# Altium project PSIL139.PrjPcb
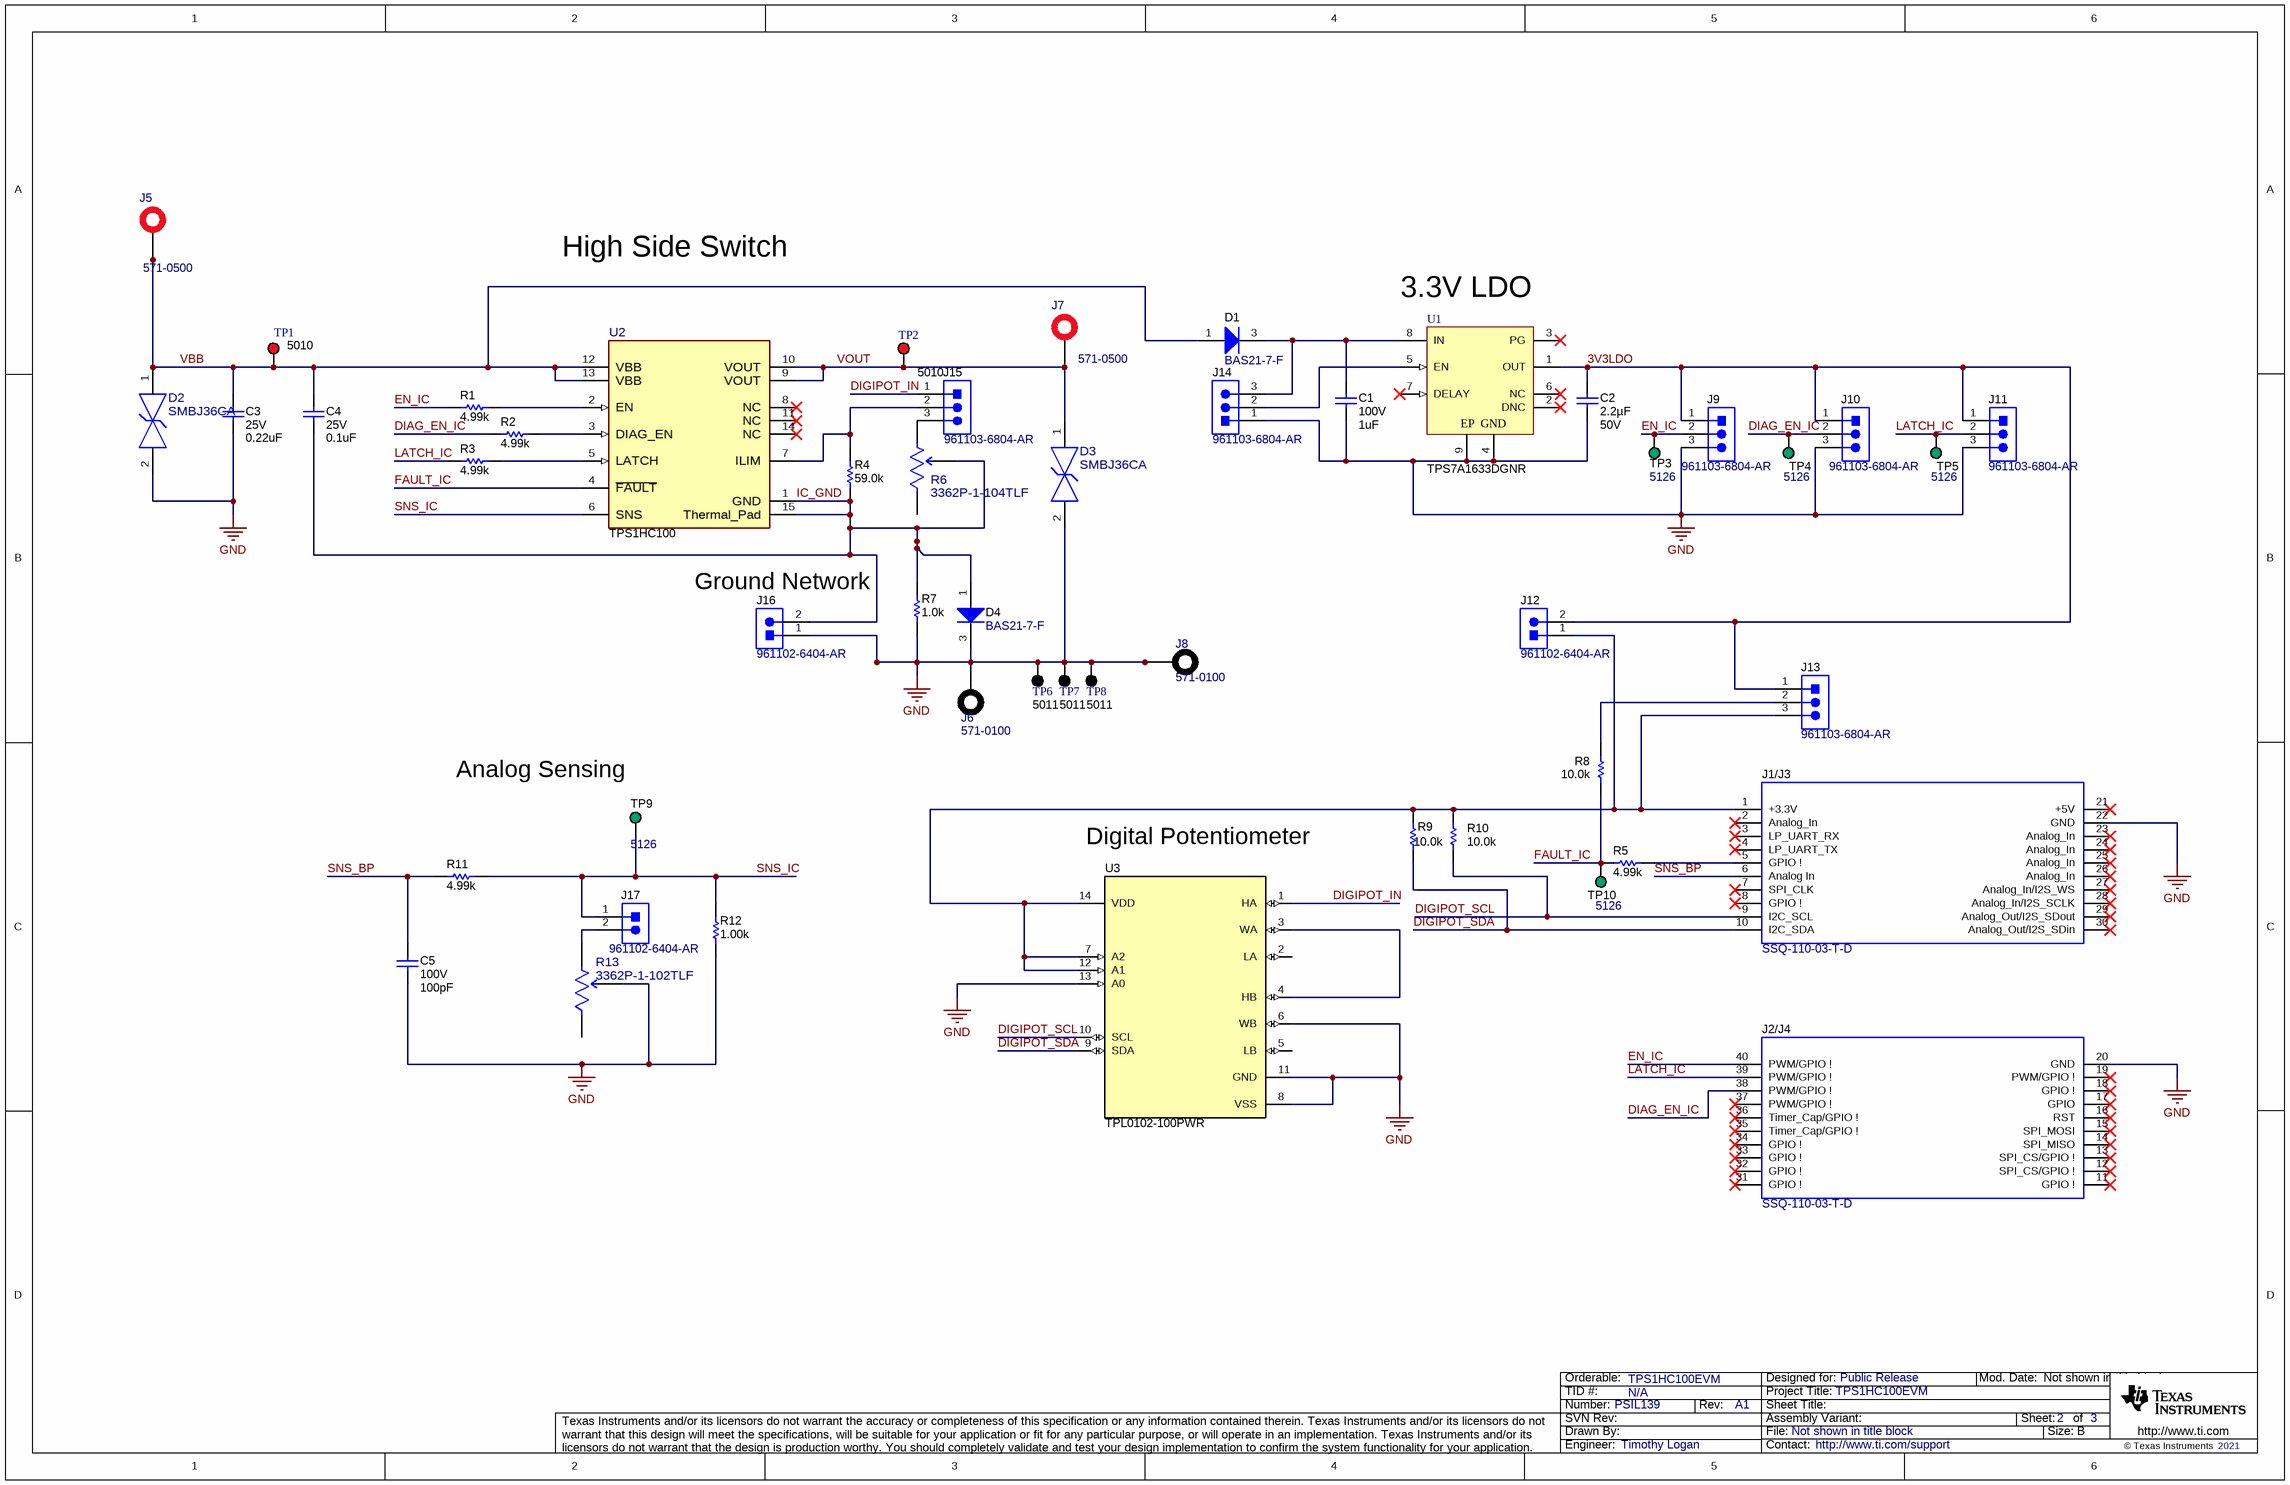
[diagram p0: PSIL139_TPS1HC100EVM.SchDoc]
CopyrightYear: 2021; EVM_Orderable: TPS1HC100EVM; PCB_Layout: Timothy Logan; PCB_Rev: A1; PRJ_Customer: Public Release; PRJ_Engineer: Timothy Logan; PRJ_Number: PSIL139; PRJ_Title: TPS1HC100EVM; SCH_Rev: A1; TechSupport: http://www.ti.com/support; TID: N/A
2 sheets, 66 parts. Net scope: global (net labels, ports and power ports of the same name join across sheets).
Board file: PSIL139_TPS1HC100EVM_PCB.PcbDoc
Sheets:
  PSIL139_TPS1HC100EVM.SchDoc
  PSIL139_Hardware.SchDoc

## Sheet PSIL139_TPS1HC100EVM.SchDoc
size 431 x 279 mm; Date: Not shown in title block; ApprovedBy: Not shown in title block; CheckedBy: Not shown in title block; Author: Not shown in title block; CompanyName: Not shown in title block; Engineer: Not shown in title block; Organization: Not shown in title block; Address1: Not shown in title block; Address2: Not shown in title block; Address3: Not shown in title block; Address4: Not shown in title block; DocumentNumber: 2; Revision: Use project parameter SCH_Rev; SheetNumber: 2; SheetTotal: 3; PageSetup: Record=PageOptions¦CenterHorizontal=True¦CenterVertical=True¦PrintScale=1.00¦XCorrection=1.00¦YCorrection=1.00¦PrintKind=0¦BorderSize=5000000¦LeftOffset=0¦BottomOffset=0¦Orientation=2¦PaperLength=1000¦PaperWidth=1000¦Scale=100¦PaperSource=15¦PrintQuality=600¦MediaType=1¦DitherType=10¦PaperKind=Letter¦PrintScaleMode=1

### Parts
C1  VDC_V: 100V  ValueDisplayed: 1uF  [0805_HV]  (hidden comment: CGA4J3X7S2A105K125AB)
C2  Cap_F: 2.2µF  VDC_V: 50V  [0805_HV]  (hidden comment: CGA4J3X7R1H225K125AB)
C3  VDC_V: 25V  ValueDisplayed: 0.22uF  [0603]  (hidden comment: CGA3E3X8R1E224K080AB)
C4  VDC_V: 25V  ValueDisplayed: 0.1uF  [0603]  (hidden comment: CGA3E2X8R1E104K080AA)
C5  VDC_V: 100V  ValueDisplayed: 100pF  [0603]  (hidden comment: GCM1885C2A101JA16D)
D1  BAS21-7-F  [SOT-23L]
D2  SMBJ36CA  [FP-SMBJ36CA_DO-214AA-0]
D3  SMBJ36CA  [FP-SMBJ36CA_DO-214AA-0]
D4  BAS21-7-F  [SOT-23L]
J1/J3  SSQ-110-03-T-D  [BoosterPack_40pin_J1J3]
J2/J4  SSQ-110-03-T-D  [BoosterPack_40pin_J2J4]
J5  571-0500  [571-0500]
J6  571-0100  [571-0100]
J7  571-0500  [571-0500]
J8  571-0100  [571-0100]
J9  961103-6804-AR  [3M_961103-68]
J10  961103-6804-AR  [3M_961103-68]
J11  961103-6804-AR  [3M_961103-68]
J12  961102-6404-AR  [3M_961102-6404-AR]
J13  961103-6804-AR  [3M_961103-68]
J14  961103-6804-AR  [3M_961103-68]
J15  961103-6804-AR  [3M_961103-68]
J16  961102-6404-AR  [3M_961102-6404-AR]
J17  961102-6404-AR  [3M_961102-6404-AR]
R1  ValueDisplayed: 4.99k  [0603]  (hidden comment: CRCW06034K99FKEA)
R2  ValueDisplayed: 4.99k  [0603]  (hidden comment: CRCW06034K99FKEA)
R3  ValueDisplayed: 4.99k  [0603]  (hidden comment: CRCW06034K99FKEA)
R4  ValueDisplayed: 59.0k  [0805_HV]  (hidden comment: ERJ-6ENF5902V)
R5  ValueDisplayed: 4.99k  [0603]  (hidden comment: CRCW06034K99FKEA)
R6  3362P-1-104TLF  [FP-3362P-1-104TLF_PTH_TRIMMER_6MM60_6MM99-MFG]
R7  ValueDisplayed: 1.0k  [0805_HV]  (hidden comment: ERJ-6GEYJ102V)
R8  ValueDisplayed: 10.0k  [0603]  (hidden comment: ERA-3ARW103V)
R9  ValueDisplayed: 10.0k  [0603]  (hidden comment: ERA-3ARW103V)
R10  ValueDisplayed: 10.0k  [0603]  (hidden comment: ERA-3ARW103V)
R11  ValueDisplayed: 4.99k  [0603]  (hidden comment: CRCW06034K99FKEA)
R12  ValueDisplayed: 1.00k  [0805_HV]  (hidden comment: ERJ-P06F1001V)
R13  3362P-1-102TLF  [FP-3362P-1-102TLF_PTH_POT_6MM6_6MM99-MFG]
TP1  5010  [Keystone5010]
TP2  5010  [Keystone5010]
TP3  5126  [Keystone5126]
TP4  5126  [Keystone5126]
TP5  5126  [Keystone5126]
TP6  5011  [Keystone5011]
TP7  5011  [Keystone5011]
TP8  5011  [Keystone5011]
TP9  5126  [Keystone5126]
TP10  5126  [Keystone5126]
U1  TPS7A1633DGNR  [DGN0008C_N]
U2  TPS1HC100  [PWP0014C-MFG]
U3  TPL0102-100PWR  [PW0014A_N]

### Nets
GND: C1.2 C2.2 C3.2 C5.1 D2.2 D3.2 D4.3(K) J1/J3.22(GND) J2/J4.20(GND) J6.1 J6.2 J8.1 J8.2 J9.3 J10.3 J11.3 J14.1 J16.1 R7.1 R12.2 R13.2(WIPER) TP6.1 TP7.1 TP8.1 U1.4(GND) U1.9(EP) U3.6(WB) U3.8(VSS) U3.11(GND) U3.13(A0)
3V3LDO: C2.1 J9.1 J10.1 J11.1 J12.2 J13.1 U1.1(OUT)
DIAG_EN_IC: J2/J4.38(PWM/GPIO_!) J10.2 R2.1 TP4.1
DIGIPOT_IN: J15.1 U3.1(HA)
DIGIPOT_SCL: J1/J3.9(I2C_SCL) R10.1 U3.10(SCL)
DIGIPOT_SDA: J1/J3.10(I2C_SDA) R9.1 U3.9(SDA)
EN_IC: J2/J4.40(PWM/GPIO_!) J9.2 R1.1 TP3.1
FAULT_IC: R5.1 R8.1 TP10.1 U2.4(~{FAULT})
IC_GND: C4.2 D4.1(A) J16.2 R4.1 R6.2(WIPER) R7.2 U2.1(GND) U2.15(Thermal_Pad)
LATCH_IC: J2/J4.39(PWM/GPIO_!) J11.2 R3.1 TP5.1
SNS_BP: C5.2 J1/J3.6(Analog_In) R11.1
SNS_IC: J17.1 R11.2 R12.1 TP9.1 U2.6(SNS)
VBB: C3.1 C4.1 D1.1(A) D2.1 J5.1 J5.2 TP1.1 U2.12(VBB) U2.13(VBB)
VOUT: D3.1 J7.1 J7.2 TP2.1 U2.9(VOUT) U2.10(VOUT)
NetC1_1: C1.1 D1.3(K) J14.3 U1.8(IN)
NetJ1/J3_1: J1/J3.1(+3.3V) J12.1 J13.3 R9.2 R10.2 U3.7(A2) U3.12(A1) U3.14(VDD)
NetJ1/J3_5: J1/J3.5(GPIO_!) R5.2
NetJ13_2: J13.2 R8.2
NetJ14_2: J14.2 U1.5(EN)
NetJ15_2: J15.2 R4.2 U2.7(ILIM)
NetJ15_3: J15.3 R6.1(CCW)
NetJ17_2: J17.2 R13.3(CW)
NetR1_2: R1.2 U2.2(EN)
NetR2_2: R2.2 U2.3(DIAG_EN)
NetR3_2: R3.2 U2.5(LATCH)
NetU3_3: U3.3(WA) U3.4(HB)

Not connected (* = marked no-connect by the designer): J1/J3 2(Analog_In)* 3(LP_UART_RX)* 4(LP_UART_TX)* 7(SPI_CLK)* 8(GPIO_!)* 21(+5V)* 23(Analog_In)* 24(Analog_In)* 25(Analog_In)* 26(Analog_In)* 27(Analog_In/I2S_WS)* 28(Analog_In/I2S_SCLK)* 29(Analog_Out/I2S_SDout)* 30(Analog_Out/I2S_SDin)*; J2/J4 11(GPIO_!)* 12(SPI_CS/GPIO_!)* 13(SPI_CS/GPIO_!)* 14(SPI_MISO)* 15(SPI_MOSI)* 16(RST)* 17(GPIO)* 18(GPIO_!)* 19(PWM/GPIO_!)* 31(GPIO_!)* 32(GPIO_!)* 33(GPIO_!)* 34(GPIO_!)* 35(Timer_Cap/GPIO_!)* 36(Timer_Cap/GPIO_!)* 37(PWM/GPIO_!)*; R6 3(CW); R13 1(CCW); U1 2(DNC)* 3(PG)* 6(NC)* 7(DELAY)*; U2 8(NC)* 11(NC)* 14(NC)*; U3 2(LA) 5(LB)

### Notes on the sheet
- High Side Switch
- (near U1) 3.3V LDO
- (near J16) Ground Network
- (near TP9) Analog Sensing
- Digital Potentiometer

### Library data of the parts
C1 = CMP-0007980-2: CAP, CERM, 1 uF, 100 V, +/- 10%, X7S, AEC-Q200 Grade 1, 0805; Manufacturer: TDK; TaMin_C: -55°C; ESR_ohm: 8.255m; Polarized: N; SizeAreaWB_mm2: 6.75; Value1: 0.008255 ohm; U/M: EA; Value: 1uF; TaMax_C: 125°C; SizeZ_mm: 1.45; SizeX_mm: 2; SizeY_mm: 1.25; Cap_Case: 0805; SizeArea_mm2: 2.5; AEC Qualified: Y; Cap_F: 1µF; IRMS_A: 2.27442A; AEC Grade: 1; AEC Category: Q200
C2 = CMP-0007977-1: CAP, CERM, 2.2 uF, 50 V, +/- 10%, X7R, AEC-Q200 Grade 1, 0805; Manufacturer: TDK; TaMin_C: -55°C; ESR_ohm: 3.288m; Polarized: N; SizeAreaWB_mm2: 6.75; Value1: 0.003288 ohm; U/M: EA; Value: 2.2uF; TaMax_C: 125°C; SizeZ_mm: 1.45; SizeX_mm: 2; SizeY_mm: 1.25; Cap_Case: 0805; SizeArea_mm2: 2.5; AEC Qualified: Y; IRMS_A: 3.60029A; AEC Grade: 1; AEC Category: Q200
C3 = CMP-0007103-2: CAP, CERM, 0.22 uF, 25 V, +/- 10%, X8R, AEC-Q200 Grade 0, 0603; Manufacturer: TDK; TaMin_C: -55°C; Polarized: N; SizeAreaWB_mm2: 4.68; Value1: Unknown; U/M: EA; Value: 0.22uF; TaMax_C: 150°C; SizeZ_mm: 1; SizeX_mm: 1.6; SizeY_mm: 0.8; SizeArea_mm2: 1.28; AEC Qualified: Y; Cap_F: 220nF; AEC Grade: 0; AEC Category: Q200
C4 = CMP-0007090-1: CAP, CERM, 0.1 uF, 25 V, +/- 10%, X8R, AEC-Q200 Grade 0, 0603; Manufacturer: TDK; TaMin_C: -55°C; Polarized: N; SizeAreaWB_mm2: 4.68; Value1: Unknown; U/M: EA; Value: 0.1uF; TaMax_C: 150°C; SizeZ_mm: 1; SizeX_mm: 1.6; SizeY_mm: 0.8; SizeArea_mm2: 1.28; AEC Qualified: Y; Cap_F: 100nF; AEC Grade: 0; AEC Category: Q200
C5 = CMP-0007130-1: CAP, CERM, 100 pF, 100 V, +/- 5%, C0G/NP0, AEC-Q200 Grade 1, 0603; Manufacturer: MuRata; TaMin_C: -55°C; Polarized: N; SizeAreaWB_mm2: 4.68; Value1: Unknown; U/M: EA; TaMax_C: 125°C; SizeZ_mm: 1; SizeX_mm: 1.6; SizeY_mm: 0.8; SizeArea_mm2: 1.28; AEC Qualified: Y; AEC Category: Q200; Value: 100pF
D1 D4 = CMP-0076901-1: Diode, Switching, 200 V, 0.2 A, SOT-23; Manufacturer: Diodes Inc.; SizeAreaWB_mm2: 14.0; Vr_V: 200V; SizeArea_mm2: 7.5; TJmax_C: 150°C; AEC Category: Q101; Value: 200V; SizeZ_mm: 1.1; Green_REACh: Passed; Io_A: 200mA; Vf_V: 1.25V; SizeY_mm: 3.0; Green_Lifecycle: Active; U/M: EA; Value1: 0.2A; SizeX_mm: 2.5
D2 D3 = CMP-0086728-1: Diode TVS Single Bi-Dir 36V 600W 2-Pin SMB; Manufacturer: Littelfuse; SizeZ_mm: 2.61mm; Ipp: 10.4µA
J1/J3 = CMP-0003837-4: Receptacle, 2.54mm, 10x2, Tin, TH; Alternate PartNumber: CRD-081413-A-G; Manufacturer: Samtec; Alternate Manufacturer: Major League Electronics; Note: Booster Pack 40 pin J1 and J3; Green_Lifecycle: Active; Green_REACh: Incomplete
J2/J4 = CMP-0078266-2: Receptacle, 2.54mm, 10x2, Tin, TH; Alternate PartNumber: CRD-081413-A-G; Manufacturer: Samtec; Alternate Manufacturer: Major League Electronics; Note: Booster Pack 40 pin J2 and J4; Green_REACh: Incomplete; Green_Lifecycle: Active
J5 J7 = CMP-0055393-2: Standard Banana Jack, insulated, 10A, red; Manufacturer: DEM Manufacturing; CT: TRUE; Green_REACh: Incomplete; CNHeader: FALSE; Green_Lifecycle: Not Set
J6 J8 = CMP-0055389-3: Standard Banana Jack, insulated, 10A, black; Manufacturer: DEM Manufacturing; Green_REACh: Incomplete; Green_Lifecycle: Not Set
J9-J11 J13-J15 = CMP-0075356-1: Header, 2.54mm, 3x1, Gold, TH; Manufacturer: 3M; CNHeader: True; Current_A: 2A; Shrouded: N; Gender: Male; Row_Count: 1; Pitch_mm: 2.54; CT: False; Cert_UL: Y
J12 J16 J17 = CMP-0075197-1: Header, 2.54mm, 2x1, TH; Manufacturer: 3M; CNHeader: True; Current_A: 2A; Green_Lifecycle: Active; Shrouded: N; Gender: Male; Green_REACh: Passed; Voltage_V: 1kV; Row_Count: 1; Pitch_mm: 2.54; ContactFinish: Gold; CT: False; Cert_UL: Y
R1-R3 R5 R11 = CMP-0022458-4: RES, 4.99 k, 1%, 0.1 W, AEC-Q200 Grade 0, 0603; Manufacturer: Vishay-Dale; Power_W: 100mW; TempCo: 100 ppm/C; Value_Code: 4k99; Value: 4.99k; EIA_Code: E96; SizeX_mm: 1.6; SizeY_mm: 0.8; SizeZ_mm: 1; Value2: 0.1W; SizeArea_mm2: 1.28; AEC Qualified: Y; VDC_V: 75V; AEC Category: Q200; AEC Grade: 0
R4 = CMP-0021756-3: RES, 59.0 k, 1%, 0.125 W, AEC-Q200 Grade 0, 0805; Manufacturer: Panasonic; Power_W: 125mW; TempCo: 100 ppm/C; Value_Code: 59k0; Value: 59.0k; EIA_Code: E96; Res_ohm: 59k; SizeX_mm: 2; SizeY_mm: 1.25; SizeZ_mm: 1.45; Value2: 0.125W; SizeArea_mm2: 2.5; AEC Qualified: Y; AEC Category: Q200; AEC Grade: 0; SizeAreaWB_mm2: 6.75
R6 = CMP-0091455-1: Res Cermet Trimmer 100K Ohm 10% 1/2W 1(Elec)/1(Mech)Turn 5mm (6.71 X 7.04 X 14.63mm) Pin Thru-Hole Tube; Manufacturer: Bourns; Value: 100kΩ; AEC Qualified: No; TempCo: 100ppm/°C; SizeZ_mm: 15.06mm; Power_W: 0.5W; Standoff Height: 0.38mm
R7 = CMP-0020619-3: RES, 1.0 k, 5%, 0.125 W, AEC-Q200 Grade 0, 0805; Manufacturer: Panasonic; Power_W: 125mW; TempCo: 200 ppm/C; Value_Code: 1k00; Value: 1.0k; EIA_Code: E24; Res_ohm: 1k; SizeX_mm: 2; SizeY_mm: 1.25; SizeZ_mm: 1.45; Value2: 0.125W; SizeArea_mm2: 2.5; AEC Qualified: Y; VDC_V: 150V; AEC Category: Q200; AEC Grade: 0; SizeAreaWB_mm2: 6.75
R8-R10 = CMP-0086251-1: RES, 10.0 k, 0.05%, 0.1 W, AEC-Q200 Grade 0, 0603; Manufacturer: Panasonic; Res_ohm: 10k; Value: 10.0k; SizeY_mm: 0.8; SizeArea_mm2: 1.28; SizeAreaWB_mm2: 4.68; AEC Grade: 0; Power_W: 100mW; SizeX_mm: 1.6; Value2: 0.1W; Value_Code: 10k0; SizeZ_mm: 1; AEC Qualified: Y; AEC Category: Q200; TempCo: 10 ppm/C
R12 = CMP-0021848-2: RES, 1.00 k, 1%, 0.25 W, 0805; Manufacturer: Panasonic; Power_W: 250mW; TempCo: 100 ppm/C; Value_Code: 1k00; U/M: EA; Value: 1.00k; EIA_Code: E96; Res_ohm: 1k; SizeX_mm: 2; SizeY_mm: 1.25; SizeZ_mm: 1.45; Value2: 0.25W; SizeArea_mm2: 2.5; VDC_V: 400V; AEC Category: Q200
R13 = CMP-0091381-1: 1 kOhms 0.5W, 1/2W PC Pins Through Hole Trimmer Potentiometer Cermet 1 Turn Top Finger Adjustment; Manufacturer: Bourns; Power_W: 500mW; TempCo: 100ppm/°C; Value: 1k; Standoff Height: 0.38mm; SizeZ_mm: 5.13mm; Tolerance_%: 10%; AEC Qualified: No
TP1 TP2 = CMP-0055147-1: Test Point, Multipurpose, Red, TH; Manufacturer: Keystone; CNHeader: FALSE; Green_Lifecycle: Active; Green_REACh: Passed; ContactFinish: Silver; CT: TRUE
TP3-TP5 TP9 TP10 = CMP-0055158-1: Test Point, Multipurpose, Green, TH; Manufacturer: Keystone; CNHeader: FALSE; Green_Lifecycle: Active; Green_REACh: Passed; ContactFinish: Silver; CT: TRUE
TP6-TP8 = CMP-0055148-1: Test Point, Multipurpose, Black, TH; Manufacturer: Keystone; CNHeader: FALSE; Green_Lifecycle: Active; Green_REACh: Passed; ContactFinish: Silver; CT: TRUE
U1 = CMP-0035936-2: Single Output LDO, 100 mA, Fixed 3.3 V Output, 3 to 60 V Input, with Enable and Power Good, 8-pin MSOP (DGN), -40 to 125 degC, Green (RoHS & no Sb/Br); Manufacturer: Texas Instruments; Vin(Max)(V): 60; SubFamily: Single Channel LDO; Iout(Max)(A): 0.1; Power Good: TRUE; Vin(Min)(V): 3; Fixed Output Options(V): 3.3; Iq(Typ)(mA): 0.004; Rating: Catalog; Accuracy(%): 2; AEC Category: Q200; AEC Qualified: N; CompType: IC; SizeAreaWB_mm2: 23.6; SizeArea_mm2: 14.7; SizeX_mm: 4.9; SizeY_mm: 3.0; SizeZ_mm: 1.1
U2 = CMP-0091243-1: 100-mΩ Single-Channel Smart High-Side Power Switch, HTSSOP14; Manufacturer: Texas Instruments; TaMin_C: -40°C; Min Supply Voltage: 2.6V; SizeZ_mm: 1.2mm; Standoff Height: 0.05mm; TJmax_C: +150°C; Nominal Supply Current: 3mA; Max Supply Voltage: 28V; Number Of Outputs: 1; TaMax_C: +125°C; AEC Qualified: Yes; AEC Grade: Grade 1
U3 = CMP-0066591-1: 256-Taps Dual-Channel Digital Potentiometer With I2C Interface and Nonvolatile Memory, PW0014A (TSSOP-14); Alternate Manufacturer: Texas Instruments; SizeAreaWB_mm2: 58.8; U/M: EA; SizeZ_mm: 1.2; SizeX_mm: 6.4; SizeY_mm: 5.0; SizeArea_mm2: 32.0; CompType: IC

## Sheet PSIL139_Hardware.SchDoc
size 431 x 279 mm; Date: Not shown in title block; ApprovedBy: Not shown in title block; CheckedBy: Not shown in title block; Author: Not shown in title block; CompanyName: Not shown in title block; Engineer: Not shown in title block; Organization: Not shown in title block; Address1: Not shown in title block; Address2: Not shown in title block; Address3: Not shown in title block; Address4: Not shown in title block; DocumentNumber: 3; Revision: Use project parameter SCH_Rev; SheetNumber: 3; SheetTotal: 3; PageSetup: Record=PageOptions¦CenterHorizontal=True¦CenterVertical=True¦PrintScale=1.00¦XCorrection=1.00¦YCorrection=1.00¦PrintKind=0¦BorderSize=5000000¦LeftOffset=0¦BottomOffset=0¦Orientation=2¦PaperLength=1000¦PaperWidth=1000¦Scale=100¦PaperSource=15¦PrintQuality=600¦MediaType=1¦DitherType=10¦PaperKind=Letter¦PrintScaleMode=1
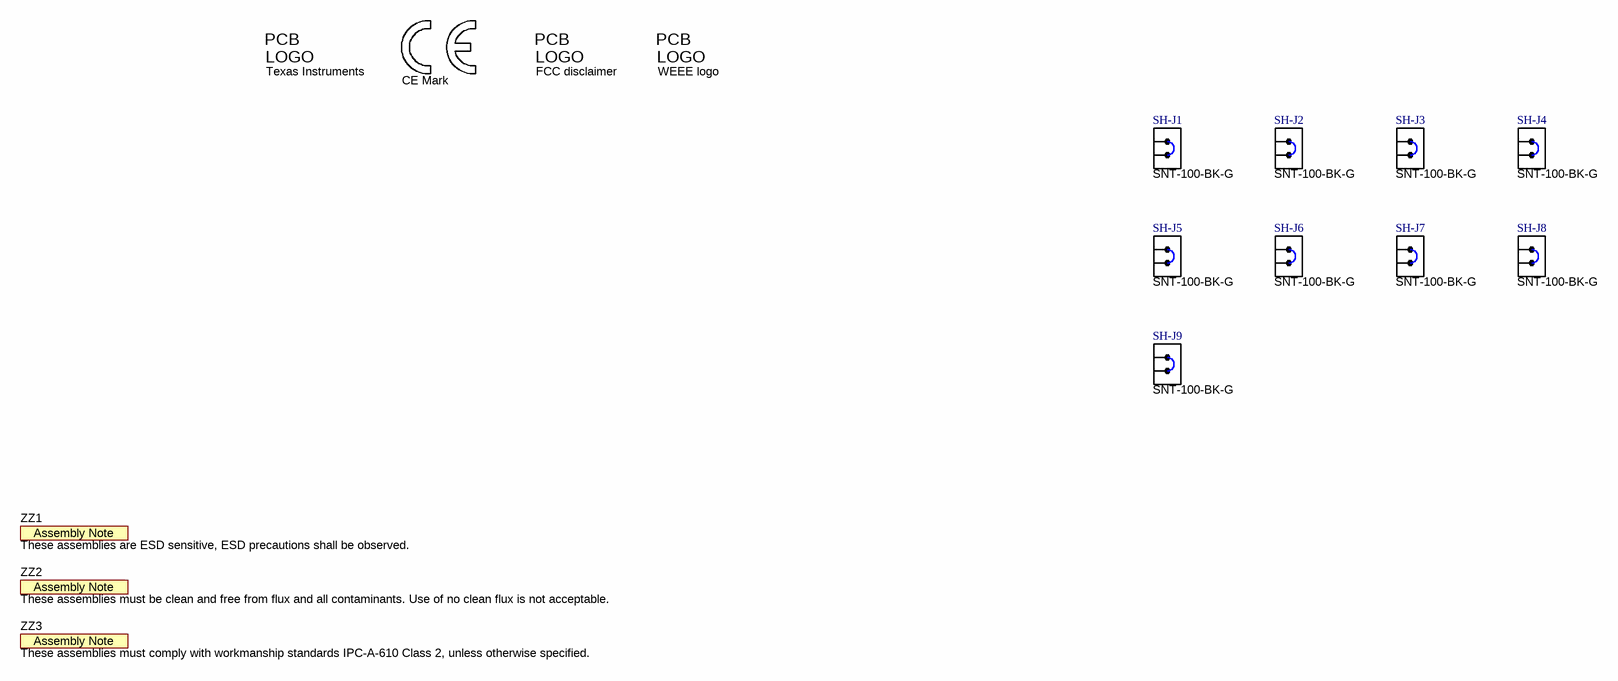
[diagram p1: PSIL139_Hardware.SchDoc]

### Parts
Logo1  CE Mark  [CE_Mark_5mm]  (no BOM)
Logo2  Texas Instruments  [TI_Stacked_Overlay_Small]  (no BOM)
Logo3  FCC disclaimer  [FCC_disclaimer]  (no BOM)
Logo4  WEEE logo  [WEEE_Minimum]  (no BOM)
SH-J1  SNT-100-BK-G  [SNT-100-BK-G]
SH-J2  SNT-100-BK-G  [SNT-100-BK-G]
SH-J3  SNT-100-BK-G  [SNT-100-BK-G]
SH-J4  SNT-100-BK-G  [SNT-100-BK-G]
SH-J5  SNT-100-BK-G  [SNT-100-BK-G]
SH-J6  SNT-100-BK-G  [SNT-100-BK-G]
SH-J7  SNT-100-BK-G  [SNT-100-BK-G]
SH-J8  SNT-100-BK-G  [SNT-100-BK-G]
SH-J9  SNT-100-BK-G  [SNT-100-BK-G]
ZZ1  These assemblies are ESD sensitive, ESD precautions shall be observed.  [AssemblyNote]  (no BOM)
ZZ2  These assemblies must be clean and free from flux and all contaminants. Use of no clean flux is not acceptable.  [AssemblyNote]  (no BOM)
ZZ3  These assemblies must comply with workmanship standards IPC-A-610 Class 2, unless otherwise specified.  [AssemblyNote]  (no BOM)

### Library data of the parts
Logo1 = CMP-0074844-1: SymbolCreator: a0412235
Logo2 = CMP-0074838-1: Texas Instrument Corporate Signature; SymbolCreator: a0412235; Lib Reference: TI_Logo; Library Reference: Logo
Logo3 = CMP-0074847-1: FCC_disclaimer; Library Reference: Logo
Logo4 = CMP-0074769-1
SH-J1-SH-J9 = CMP-0003623-1: Shunt, 100mil, Gold plated, Black; Alternate PartNumber: 969102-0000-DA; Manufacturer: Samtec; Alternate Manufacturer: 3M; Value: 1x2
ZZ1 = CMP-0077236-1
ZZ2 = CMP-0077237-1
ZZ3 = CMP-0077238-1

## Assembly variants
001: not fitted D2 D3 R4 R12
